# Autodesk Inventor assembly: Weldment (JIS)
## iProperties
Length Units: 11269
Angle Units: 11283
Time Units: 11279
Mass Units: 11290
Length Display Precision: 3
Angle Display Precision: 2
Part Number: Weldment (JIS)
Document SubType Name: Weldment
Created: 2002-06
Designer: smithga
Created: 2002-08
Control State: 0
Master: False
Shininess: 64.0
Angle Units: 11279
Time Units: 11290
Mass Units: 11283
Compacted: True
Density: 0.0
Volumn: 0.0
Area: 0.0
PropertySet Name: Model Information
